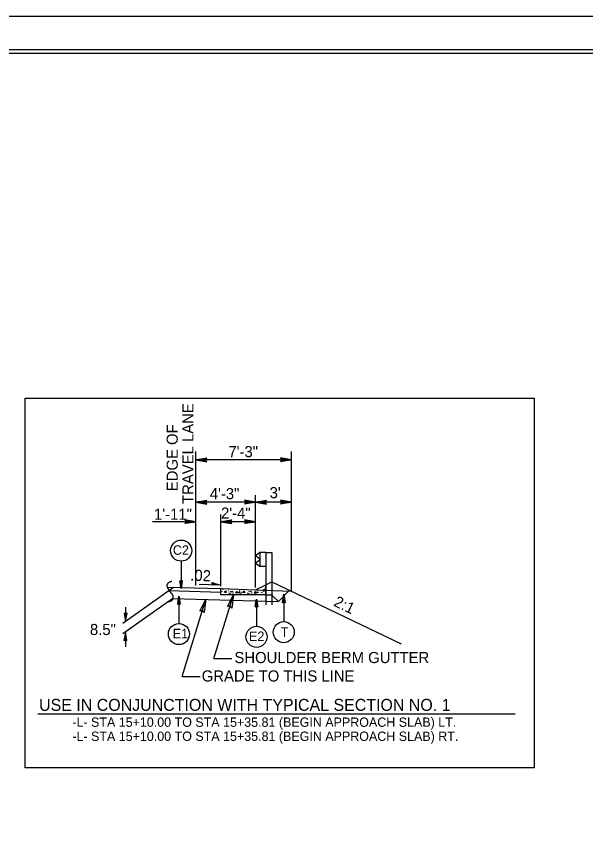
# Model space of a CAD drawing. Extents: x 55823 to 57507, y 47399 to 48499.
# Drawn here: x 56033 to 56415, y 47952 to 48499 of the extents above; entities that cross this region are included whole.
import ezdxf

# ---------------------------------------------------------------- set-up
doc = ezdxf.new("R2010")
doc.units = 0
for name, color, linetype in [('Old_Level_1', 7, 'Continuous'), ('Old_Level_11', 7, 'Continuous'), ('Old_Level_2', 7, 'Continuous'), ('Old_Level_20', 7, 'Continuous'), ('Sheet Plot Border Inside CELL', 7, 'Continuous'), ('Sheet Plot Border Outside CELL', 7, 'Continuous'), ('Sheet Typical CELL', 7, 'Continuous'), ('Typical Curb CELL', 7, 'Continuous')]:
    doc.layers.add(name, color=color, linetype=linetype)

msp = doc.modelspace()

# ---------------------------------------------------------------- linework, layer by layer
at = {"layer": 'Old_Level_1'}
for p, q in [((56153.74, 48117.93), (56153.74, 48207.72)), ((56217.76, 48114.25), (56217.76, 48207.72)), ((56217.76, 48202.2), (56153.74, 48202.2)), ((56153.75, 48202.17), (56161.12, 48203.47)), ((56153.75, 48202.17), (56160.98, 48203.29)), ((56160.84, 48203.1), (56153.75, 48202.17)), ((56153.75, 48202.17), (56160.7, 48202.91)), ((56160.57, 48202.73), (56153.75, 48202.17)), ((56153.75, 48202.17), (56160.43, 48202.54)), ((56160.3, 48202.36), (56153.75, 48202.17)), ((56153.75, 48202.17), (56161.12, 48200.87)), ((56160.98, 48201.06), (56153.75, 48202.17)), ((56153.75, 48202.17), (56160.84, 48201.24)), ((56160.7, 48201.43), (56153.75, 48202.17)), ((56153.75, 48202.17), (56160.57, 48201.62)), ((56160.43, 48201.8), (56153.75, 48202.17)), ((56153.75, 48202.17), (56160.3, 48201.99)), ((56160.16, 48202.17), (56153.75, 48202.17)), ((56160.16, 48202.17), (56161.12, 48203.47)), ((56161.12, 48200.87), (56160.16, 48202.17)), ((56217.76, 48202.2), (56210.4, 48203.5)), ((56210.4, 48203.5), (56211.35, 48202.2)), ((56217.76, 48202.2), (56210.4, 48200.9)), ((56211.35, 48202.2), (56210.4, 48200.9)), ((56210.53, 48203.31), (56217.76, 48202.2)), ((56217.76, 48202.2), (56210.53, 48201.08)), ((56217.76, 48202.2), (56210.67, 48203.13)), ((56210.67, 48201.27), (56217.76, 48202.2)), ((56210.81, 48202.94), (56217.76, 48202.2)), ((56217.76, 48202.2), (56210.81, 48201.46)), ((56217.76, 48202.2), (56210.94, 48202.76)), ((56210.94, 48201.64), (56217.76, 48202.2)), ((56211.08, 48202.57), (56217.76, 48202.2)), ((56217.76, 48202.2), (56211.08, 48201.83)), ((56217.76, 48202.2), (56211.21, 48202.39)), ((56211.21, 48202.01), (56217.76, 48202.2)), ((56211.35, 48202.2), (56217.76, 48202.2)), ((56193.74, 48116.69), (56193.74, 48178.64)), ((56153.74, 48173.91), (56161.11, 48175.21)), ((56153.74, 48173.91), (56160.97, 48175.03)), ((56160.83, 48174.84), (56153.74, 48173.91)), ((56153.74, 48173.91), (56160.7, 48174.65)), ((56160.56, 48174.47), (56153.74, 48173.91)), ((56153.74, 48173.91), (56160.43, 48174.28)), ((56160.29, 48174.1), (56153.74, 48173.91)), ((56193.74, 48173.91), (56153.74, 48173.91)), ((56153.74, 48173.91), (56161.11, 48172.61)), ((56160.97, 48172.8), (56153.74, 48173.91)), ((56153.74, 48173.91), (56160.83, 48172.98)), ((56160.7, 48173.17), (56153.74, 48173.91)), ((56153.74, 48173.91), (56160.56, 48173.35)), ((56160.43, 48173.54), (56153.74, 48173.91)), ((56153.74, 48173.91), (56160.29, 48173.72)), ((56160.15, 48173.91), (56153.74, 48173.91)), ((56160.15, 48173.91), (56161.11, 48175.21)), ((56161.11, 48172.61), (56160.15, 48173.91)), ((56193.74, 48173.91), (56186.37, 48175.21)), ((56186.37, 48175.21), (56187.33, 48173.91)), ((56193.74, 48173.91), (56186.37, 48172.61)), ((56187.33, 48173.91), (56186.37, 48172.61)), ((56186.51, 48175.02), (56193.74, 48173.91)), ((56193.74, 48173.91), (56186.51, 48172.79)), ((56193.74, 48173.91), (56186.65, 48174.84)), ((56186.65, 48172.98), (56193.74, 48173.91)), ((56186.78, 48174.65), (56193.74, 48173.91)), ((56193.74, 48173.91), (56186.78, 48173.17)), ((56193.74, 48173.91), (56186.92, 48174.47)), ((56186.92, 48173.35), (56193.74, 48173.91)), ((56187.05, 48174.28), (56193.74, 48173.91)), ((56193.74, 48173.91), (56187.05, 48173.54)), ((56193.74, 48173.91), (56187.19, 48174.1)), ((56187.19, 48173.72), (56193.74, 48173.91)), ((56187.33, 48173.91), (56193.74, 48173.91)), ((56193.74, 48173.91), (56201.11, 48175.21)), ((56193.74, 48173.91), (56200.97, 48175.03)), ((56200.83, 48174.84), (56193.74, 48173.91)), ((56193.74, 48173.91), (56200.7, 48174.65)), ((56200.56, 48174.47), (56193.74, 48173.91)), ((56193.74, 48173.91), (56200.43, 48174.28)), ((56200.29, 48174.1), (56193.74, 48173.91)), ((56217.76, 48173.91), (56193.74, 48173.91)), ((56193.74, 48173.91), (56201.11, 48172.61)), ((56200.97, 48172.8), (56193.74, 48173.91)), ((56193.74, 48173.91), (56200.83, 48172.98)), ((56200.7, 48173.17), (56193.74, 48173.91)), ((56193.74, 48173.91), (56200.56, 48173.35)), ((56200.43, 48173.54), (56193.74, 48173.91)), ((56193.74, 48173.91), (56200.29, 48173.72)), ((56200.15, 48173.91), (56193.74, 48173.91)), ((56200.15, 48173.91), (56201.11, 48175.21)), ((56201.11, 48172.61), (56200.15, 48173.91)), ((56217.76, 48173.91), (56210.4, 48175.21)), ((56210.4, 48175.21), (56211.35, 48173.91)), ((56217.76, 48173.91), (56210.4, 48172.61)), ((56211.35, 48173.91), (56210.4, 48172.61)), ((56210.53, 48175.02), (56217.76, 48173.91)), ((56217.76, 48173.91), (56210.53, 48172.79)), ((56217.76, 48173.91), (56210.67, 48174.84)), ((56210.67, 48172.98), (56217.76, 48173.91)), ((56210.81, 48174.65), (56217.76, 48173.91)), ((56217.76, 48173.91), (56210.81, 48173.17)), ((56217.76, 48173.91), (56210.94, 48174.47)), ((56210.94, 48173.35), (56217.76, 48173.91)), ((56211.08, 48174.28), (56217.76, 48173.91)), ((56217.76, 48173.91), (56211.08, 48173.54)), ((56217.76, 48173.91), (56211.21, 48174.1)), ((56211.21, 48173.72), (56217.76, 48173.91)), ((56211.35, 48173.91), (56217.76, 48173.91)), ((56153.74, 48160.76), (56124.7, 48160.76)), ((56153.74, 48160.76), (56146.37, 48162.06)), ((56146.37, 48162.06), (56147.33, 48160.76)), ((56153.74, 48160.76), (56146.37, 48159.46)), ((56147.33, 48160.76), (56146.37, 48159.46)), ((56146.51, 48161.88), (56153.74, 48160.76)), ((56153.74, 48160.76), (56146.51, 48159.65)), ((56153.74, 48160.76), (56146.65, 48161.69)), ((56146.65, 48159.83), (56153.74, 48160.76)), ((56146.78, 48161.5), (56153.74, 48160.76)), ((56153.74, 48160.76), (56146.78, 48160.02)), ((56153.74, 48160.76), (56146.92, 48161.32)), ((56146.92, 48160.21), (56153.74, 48160.76)), ((56147.05, 48161.14), (56153.74, 48160.76)), ((56153.74, 48160.76), (56147.05, 48160.39)), ((56153.74, 48160.76), (56147.19, 48160.95)), ((56147.19, 48160.58), (56153.74, 48160.76)), ((56147.33, 48160.76), (56153.74, 48160.76)), ((56170.41, 48117.53), (56170.41, 48165.52)), ((56170.41, 48160.76), (56177.78, 48162.06)), ((56170.41, 48160.76), (56177.64, 48161.88)), ((56177.5, 48161.69), (56170.41, 48160.76)), ((56170.41, 48160.76), (56177.37, 48161.51)), ((56177.23, 48161.32), (56170.41, 48160.76)), ((56170.41, 48160.76), (56177.1, 48161.14)), ((56176.96, 48160.95), (56170.41, 48160.76)), ((56193.74, 48160.76), (56170.41, 48160.76)), ((56170.41, 48160.76), (56177.78, 48159.46)), ((56177.64, 48159.65), (56170.41, 48160.76)), ((56170.41, 48160.76), (56177.5, 48159.84)), ((56177.37, 48160.02), (56170.41, 48160.76)), ((56170.41, 48160.76), (56177.23, 48160.21)), ((56177.1, 48160.39), (56170.41, 48160.76)), ((56170.41, 48160.76), (56176.96, 48160.58)), ((56176.82, 48160.76), (56170.41, 48160.76)), ((56176.82, 48160.76), (56177.78, 48162.06)), ((56177.78, 48159.46), (56176.82, 48160.76)), ((56193.74, 48160.76), (56186.37, 48162.06)), ((56186.37, 48162.06), (56187.33, 48160.76)), ((56193.74, 48160.76), (56186.37, 48159.46)), ((56187.33, 48160.76), (56186.37, 48159.46)), ((56186.51, 48161.88), (56193.74, 48160.76)), ((56193.74, 48160.76), (56186.51, 48159.65)), ((56193.74, 48160.76), (56186.65, 48161.69)), ((56186.65, 48159.83), (56193.74, 48160.76)), ((56186.78, 48161.5), (56193.74, 48160.76)), ((56193.74, 48160.76), (56186.78, 48160.02)), ((56193.74, 48160.76), (56186.92, 48161.32)), ((56186.92, 48160.21), (56193.74, 48160.76)), ((56187.05, 48161.14), (56193.74, 48160.76)), ((56193.74, 48160.76), (56187.05, 48160.39)), ((56193.74, 48160.76), (56187.19, 48160.95)), ((56187.19, 48160.58), (56193.74, 48160.76)), ((56187.33, 48160.76), (56193.74, 48160.76)), ((56196.59, 48140.04), (56194.25, 48138.39)), ((56200.61, 48140.04), (56196.59, 48140.04)), ((56196.59, 48140.04), (56196.59, 48130.65)), ((56200.61, 48140.04), (56200.61, 48111.77)), ((56200.61, 48140.04), (56204.64, 48140.04)), ((56204.64, 48140.04), (56204.64, 48119.93)), ((56196.59, 48135.72), (56194.25, 48137.36)), ((56196.59, 48134.97), (56194.25, 48133.33)), ((56196.59, 48135.35), (56196.59, 48135.72)), ((56196.59, 48135.35), (56196.59, 48134.97)), ((56196.59, 48130.65), (56194.25, 48132.3)), ((56200.61, 48130.65), (56196.59, 48130.65)), ((56138.7, 48116.76), (56104.6, 48092.53)), ((56134.55, 48116.87), (56170.41, 48115.94)), ((56143.79, 48116.06), (56142.88, 48121.24)), ((56143.79, 48120.56), (56142.88, 48121.24)), ((56143.79, 48116.06), (56143.01, 48121.14)), ((56143.14, 48121.04), (56143.79, 48116.06)), ((56143.79, 48116.06), (56143.27, 48120.95)), ((56143.4, 48120.85), (56143.79, 48116.06)), ((56143.79, 48116.06), (56143.53, 48120.76)), ((56143.66, 48120.66), (56143.79, 48116.06)), ((56143.79, 48116.06), (56144.7, 48121.24)), ((56144.7, 48121.24), (56143.79, 48120.56)), ((56144.57, 48121.14), (56143.79, 48116.06)), ((56143.79, 48116.06), (56144.44, 48121.04)), ((56144.31, 48120.95), (56143.79, 48116.06)), ((56143.79, 48116.06), (56144.18, 48120.85)), ((56144.05, 48120.76), (56143.79, 48116.06)), ((56143.79, 48116.06), (56143.92, 48120.66)), ((56143.79, 48120.56), (56143.79, 48116.06)), ((56155.8, 48118.95), (56169.5, 48118.57)), ((56164.62, 48119.85), (56164.66, 48119.81)), ((56164.7, 48119.75), (56164.77, 48119.75)), ((56164.76, 48119.62), (56165.24, 48119.63)), ((56165.67, 48119.49), (56164.81, 48119.53)), ((56164.85, 48119.38), (56166.2, 48119.34)), ((56164.85, 48119.25), (56166.74, 48119.18)), ((56164.85, 48118.86), (56168.66, 48118.71)), ((56164.86, 48119.16), (56167.48, 48119.02)), ((56164.86, 48119.06), (56167.79, 48118.92)), ((56164.86, 48118.77), (56169.03, 48118.62)), ((56164.88, 48118.96), (56168.25, 48118.82)), ((56200.61, 48118.54), (56204.64, 48120.56)), ((56204.64, 48119.93), (56204.64, 48111.77)), ((56135.65, 48114.67), (56170.41, 48113.64)), ((56142.32, 48110.8), (56141.4, 48105.62)), ((56141.54, 48105.71), (56142.32, 48110.8)), ((56142.32, 48110.8), (56141.67, 48105.81)), ((56141.8, 48105.91), (56142.32, 48110.8)), ((56142.32, 48110.8), (56141.93, 48106)), ((56142.06, 48106.1), (56142.32, 48110.8)), ((56142.32, 48110.8), (56142.19, 48106.19)), ((56142.32, 48110.8), (56143.23, 48105.62)), ((56142.32, 48106.29), (56142.32, 48110.8)), ((56142.45, 48106.19), (56142.32, 48110.8)), ((56142.32, 48110.8), (56142.58, 48106.1)), ((56142.71, 48106), (56142.32, 48110.8)), ((56142.32, 48110.8), (56142.84, 48105.91)), ((56142.97, 48105.81), (56142.32, 48110.8)), ((56142.32, 48110.8), (56143.1, 48105.71)), ((56165.8, 48069.12), (56178.87, 48111.77)), ((56193.74, 48115.11), (56217.76, 48114.25)), ((56200.61, 48111.77), (56204.64, 48111.77)), ((56200.61, 48111.77), (56200.61, 48105.12)), ((56200.61, 48111.77), (56204.64, 48111.65)), ((56204.64, 48111.77), (56204.64, 48105.12)), ((56204.64, 48111.65), (56208.98, 48107.32)), ((56216.51, 48114.85), (56208.98, 48107.32)), ((56138.25, 48109.4), (56104.68, 48085.55)), ((56138.25, 48109.4), (56208.98, 48107.32)), ((56141.4, 48105.62), (56142.32, 48106.29)), ((56142.32, 48106.29), (56143.23, 48105.62)), ((56144.53, 48057.14), (56160.33, 48108.75)), ((56194.29, 48108.97), (56193.38, 48103.79)), ((56193.51, 48103.89), (56194.29, 48108.97)), ((56194.29, 48108.97), (56193.64, 48103.98)), ((56193.77, 48104.08), (56194.29, 48108.97)), ((56194.29, 48108.97), (56193.9, 48104.17)), ((56194.03, 48104.27), (56194.29, 48108.97)), ((56194.29, 48108.97), (56194.16, 48104.36)), ((56194.29, 48108.97), (56195.21, 48103.79)), ((56194.29, 48104.46), (56194.29, 48108.97)), ((56194.42, 48104.36), (56194.29, 48108.97)), ((56194.29, 48108.97), (56194.55, 48104.27)), ((56194.68, 48104.17), (56194.29, 48108.97)), ((56194.29, 48108.97), (56194.81, 48104.08)), ((56194.94, 48103.98), (56194.29, 48108.97)), ((56194.29, 48108.97), (56195.07, 48103.89)), ((56193.38, 48103.79), (56194.29, 48104.46)), ((56194.29, 48104.46), (56195.21, 48103.79)), ((56165.8, 48069.12), (56177.74, 48069.12)), ((56144.53, 48057.14), (56156.56, 48057.14)), ((56047.68, 48032.1), (56367.7, 48032.1))]:
    msp.add_line(p, q, dxfattribs=at)
for points in [[(56137.58, 48120.7), (56137.56, 48120.7), (56137.53, 48120.7), (56137.51, 48120.7), (56137.48, 48120.7), (56137.46, 48120.7), (56137.44, 48120.7), (56137.44, 48120.68), (56137.39, 48120.68), (56137.34, 48120.65), (56137.27, 48120.65), (56137.2, 48120.63), (56137.1, 48120.61), (56137.03, 48120.58), (56136.96, 48120.56), (56136.86, 48120.51), (56136.76, 48120.49), (56136.67, 48120.46), (56136.57, 48120.41), (56136.48, 48120.37), (56136.38, 48120.34), (56136.31, 48120.32), (56136.21, 48120.27), (56136.14, 48120.25), (56136.07, 48120.2), (56135.97, 48120.17), (56135.9, 48120.13), (56135.83, 48120.1), (56135.76, 48120.05), (56135.69, 48120.01), (56135.64, 48119.98), (56135.57, 48119.96), (56135.52, 48119.91), (56135.47, 48119.89), (56135.4, 48119.84), (56135.38, 48119.82), (56135.3, 48119.79), (56135.28, 48119.74), (56135.26, 48119.74), (56135.21, 48119.72), (56135.16, 48119.67), (56135.14, 48119.65), (56135.06, 48119.6), (56135.04, 48119.55), (56134.97, 48119.5), (56134.9, 48119.46), (56134.85, 48119.41), (56134.8, 48119.36), (56134.73, 48119.29), (56134.7, 48119.24), (56134.66, 48119.19), (56134.63, 48119.14), (56134.61, 48119.12), (56134.59, 48119.07), (56134.56, 48119.05), (56134.54, 48119), (56134.49, 48118.95), (56134.47, 48118.88), (56134.44, 48118.83), (56134.39, 48118.76), (56134.37, 48118.69), (56134.32, 48118.62), (56134.3, 48118.54), (56134.3, 48118.47), (56134.27, 48118.38), (56134.25, 48118.31), (56134.23, 48118.23), (56134.23, 48118.16), (56134.23, 48118.07), (56134.23, 48118.02), (56134.23, 48117.95), (56134.23, 48117.87), (56134.23, 48117.8), (56134.23, 48117.75), (56134.23, 48117.68), (56134.23, 48117.63), (56134.25, 48117.56), (56134.25, 48117.47), (56134.27, 48117.42), (56134.3, 48117.32), (56134.32, 48117.25), (56134.35, 48117.18), (56134.37, 48117.08), (56134.42, 48116.99), (56134.47, 48116.89), (56134.51, 48116.8), (56134.56, 48116.7), (56134.61, 48116.6), (56134.63, 48116.51), (56134.7, 48116.39), (56134.75, 48116.27), (56134.8, 48116.17), (56134.85, 48116.08), (56134.9, 48115.98), (56134.94, 48115.86), (56134.99, 48115.77), (56135.04, 48115.67), (56135.09, 48115.57), (56135.14, 48115.48), (56135.21, 48115.38), (56135.26, 48115.31), (56135.3, 48115.21), (56135.38, 48115.12), (56135.42, 48115.02), (56135.5, 48114.93), (56135.54, 48114.83), (56135.62, 48114.76), (56135.69, 48114.66), (56135.76, 48114.57), (56135.83, 48114.47), (56135.9, 48114.38), (56135.97, 48114.26), (56136.05, 48114.16), (56136.12, 48114.09), (56136.21, 48113.97), (56136.29, 48113.9), (56136.33, 48113.8), (56136.41, 48113.73), (56136.48, 48113.63), (56136.55, 48113.56), (56136.62, 48113.46), (56136.69, 48113.39), (56136.76, 48113.3), (56136.84, 48113.22), (56136.91, 48113.13), (56136.98, 48113.03), (56137.05, 48112.96), (56137.12, 48112.87), (56137.17, 48112.79), (56137.24, 48112.72), (56137.32, 48112.63), (56137.39, 48112.55), (56137.44, 48112.48), (56137.48, 48112.43), (56137.56, 48112.34), (56137.63, 48112.27), (56137.67, 48112.19), (56137.72, 48112.12), (56137.77, 48112.05), (56137.82, 48111.95), (56137.87, 48111.88), (56137.91, 48111.79), (56137.96, 48111.69), (56138.01, 48111.6), (56138.06, 48111.52), (56138.08, 48111.43), (56138.13, 48111.36), (56138.13, 48111.28), (56138.15, 48111.21), (56138.15, 48111.14), (56138.18, 48111.04), (56138.18, 48111), (56138.2, 48110.9), (56138.2, 48110.83), (56138.23, 48110.76), (56138.23, 48110.68), (56138.23, 48110.59), (56138.23, 48110.52), (56138.23, 48110.42), (56138.25, 48110.33), (56138.25, 48110.23), (56138.25, 48110.11), (56138.25, 48110.01), (56138.25, 48109.92), (56138.25, 48109.8), (56138.25, 48109.68), (56138.25, 48109.56), (56138.25, 48109.44), (56138.23, 48109.32), (56138.2, 48109.29), (56138.2, 48109.22), (56138.18, 48109.1), (56138.15, 48109.01), (56138.11, 48108.91), (56138.08, 48108.79), (56138.01, 48108.67), (56137.96, 48108.58), (56137.89, 48108.48), (56137.84, 48108.36), (56137.77, 48108.26), (56137.67, 48108.17), (56137.6, 48108.1), (56137.53, 48108), (56137.48, 48107.95), (56137.41, 48107.88), (56137.34, 48107.83), (56137.27, 48107.78), (56137.2, 48107.74), (56137.15, 48107.69), (56137.1, 48107.64), (56137.03, 48107.62), (56136.98, 48107.57), (56136.91, 48107.55), (56136.84, 48107.52), (56136.79, 48107.47), (56136.72, 48107.45), (56136.65, 48107.4), (56136.57, 48107.38), (56136.53, 48107.35), (56136.48, 48107.33), (56136.41, 48107.31), (56136.36, 48107.31), (56136.31, 48107.28), (56136.24, 48107.26), (56136.17, 48107.23), (56136.09, 48107.21), (56136.02, 48107.19), (56135.93, 48107.16), (56135.88, 48107.14), (56135.78, 48107.11), (56135.71, 48107.09), (56135.62, 48107.07), (56135.54, 48107.04), (56135.47, 48107.04), (56135.4, 48107.02), (56135.33, 48106.99), (56135.28, 48106.97), (56135.21, 48106.97), (56135.14, 48106.95), (56135.06, 48106.92), (56134.99, 48106.9), (56134.94, 48106.87), (56134.87, 48106.85), (56134.8, 48106.85), (56134.73, 48106.8), (56134.7, 48106.8), (56134.66, 48106.78), (56134.63, 48106.78), (56134.61, 48106.73), (56134.56, 48106.73), (56134.49, 48106.71), (56134.47, 48106.68), (56134.42, 48106.68), (56134.37, 48106.63), (56134.32, 48106.63), (56134.3, 48106.61), (56134.27, 48106.61), (56134.25, 48106.61), (56134.25, 48106.63)], [(56204.64, 48120.56), (56291.34, 48078.89)]]:
    msp.add_lwpolyline(points, dxfattribs=at)
for centre, radius, start, end in [((56194.61, 48137.88), 0.628, 125.003, 235.0112), ((56194.61, 48132.81), 0.628, 125.0059, 235.0366), ((56180.67, 48168.56), 51.22, 251.5746, 257.4084), ((56162.11, 48118.92), 2.6, 355.8477, 23.7953)]:
    msp.add_arc(centre, radius, start, end, dxfattribs=at)
at = {"layer": 'Old_Level_11'}
for points in [[(56039.24, 48243.59), (56380.49, 48243.59), (56380.49, 47995.89), (56039.24, 47995.89)], [(56174.87, 48103.87), (56178.87, 48111.77), (56177.78, 48102.93), (56176.62, 48104.45)], [(56211.64, 48106.41), (56212.57, 48112.1), (56213.61, 48106.41), (56212.57, 48107.13)], [(56156.34, 48100.85), (56160.33, 48108.75), (56159.25, 48099.91), (56158.09, 48101.43)], [(56105.57, 48099.57), (56106.5, 48093.88), (56107.53, 48099.57), (56106.5, 48098.84)], [(56107.44, 48081.15), (56106.51, 48086.84), (56105.47, 48081.15), (56106.51, 48081.88)]]:
    msp.add_lwpolyline(points, close=True, dxfattribs=at)
at = {"layer": 'Old_Level_2'}
for p, q in [((56143.79, 48134.32), (56143.79, 48116.06)), ((56142.32, 48110.8), (56142.32, 48092.53)), ((56212.57, 48112.1), (56212.57, 48093.83)), ((56194.29, 48108.97), (56194.29, 48090.7)), ((56106.5, 48103.56), (56106.5, 48093.88)), ((56106.51, 48086.84), (56106.51, 48077.03))]:
    msp.add_line(p, q, dxfattribs=at)
for centre in [(56143.79, 48141.39), (56142.32, 48085.46), (56194.29, 48083.64), (56212.57, 48086.76)]:
    msp.add_circle(centre, 7.07, dxfattribs=at)
at = {"layer": 'Sheet Plot Border Inside CELL'}
msp.add_lwpolyline([(57502.66, 48476.93), (55836.16, 48476.93), (55836.16, 47421.83), (57502.66, 47421.83)], close=True, dxfattribs=at)
at = {"layer": 'Sheet Plot Border Outside CELL'}
msp.add_lwpolyline([(57507.16, 48499.38), (55823.16, 48499.38), (55823.16, 47399.38), (57507.16, 47399.38)], close=True, dxfattribs=at)
at = {"layer": 'Sheet Typical CELL'}
msp.add_lwpolyline([(57490.16, 48474.38), (55990.16, 48474.38), (55990.16, 47424.38), (57490.16, 47424.38)], close=True, dxfattribs=at)
at = {"layer": 'Typical Curb CELL'}
for p, q in [((56193.74, 48115.11), (56200.61, 48118.54)), ((56200.61, 48111.77), (56200.61, 48118.54)), ((56170.41, 48115.94), (56170.41, 48115.94)), ((56170.41, 48111.77), (56170.41, 48115.83)), ((56200.61, 48111.77), (56170.41, 48111.77)), ((56170.52, 48115.94), (56193.74, 48115.11)), ((56172.78, 48113.29), (56173.65, 48114.49)), ((56173.99, 48113.35), (56172.78, 48113.29)), ((56173.65, 48114.49), (56173.99, 48113.35)), ((56180.44, 48112.78), (56181.06, 48113.93)), ((56182.1, 48113.18), (56180.44, 48112.78)), ((56181.06, 48113.93), (56182.1, 48113.18)), ((56185.28, 48113.29), (56186.14, 48114.49)), ((56186.48, 48113.35), (56185.28, 48113.29)), ((56186.14, 48114.49), (56186.48, 48113.35)), ((56192.93, 48112.78), (56193.55, 48113.93)), ((56194.58, 48113.18), (56192.93, 48112.78)), ((56193.55, 48113.93), (56194.58, 48113.18)), ((56198.71, 48115.21), (56198.87, 48114.3)), ((56200.25, 48114.76), (56198.71, 48115.21)), ((56198.87, 48114.3), (56200.25, 48114.76))]:
    msp.add_line(p, q, dxfattribs=at)
for centre in [(56171.31, 48114.16), (56171.69, 48115.41), (56175.36, 48114.67), (56175.95, 48112.88), (56176.51, 48112.54), (56176.84, 48113.81), (56177.6, 48113.79), (56178.1, 48114.1), (56178.57, 48112.94), (56180.51, 48113.33), (56182.57, 48113.17), (56182.74, 48113.68), (56182.84, 48114.27), (56183.41, 48112.84), (56184.37, 48113.3), (56185.3, 48113.39), (56186.5, 48112.88), (56188.44, 48112.88), (56189, 48112.54), (56189.33, 48113.81), (56190.59, 48114.1), (56191.06, 48112.94), (56193, 48113.33), (56193.29, 48112.31), (56195.06, 48113.17), (56195.23, 48113.68), (56197.8, 48113.39), (56198.99, 48112.88), (56199.97, 48115.62)]:
    msp.add_circle(centre, 0.0802, dxfattribs=at)
msp.add_arc((56170.51, 48115.83), 0.104, 87.952, 180, dxfattribs=at)

# ---------------------------------------------------------------- texts
at = {"layer": 'Old_Level_1'}
for s, height, rotation, p in [('TRAVEL LANE', 7.4468, 90, (56152.07, 48172.65)), ('EDGE OF', 7.447, 90, (56141.53, 48181.19)), (' .02', 7.447, 357.1962, (56147.01, 48121.53)), ('2:1', 7.447, 334.3354, (56245.44, 48104.63))]:
    msp.add_text(s, height=height, rotation=rotation, dxfattribs=at).set_placement(p)
for s, height, p in [('7\'-3"', 7.447, (56175.49, 48204)), ('4\'-3"', 7.447, (56163, 48175.84)), ("3'", 7.447, (56203.12, 48176.49)), ('1\'-11"', 7.447, (56125.64, 48162.06)), ('2\'-4"', 7.447, (56170.52, 48162.8)), ('8.5"', 7.447, (56082.66, 48084.82)), ('SHOULDER BERM GUTTER', 7.4468, (56179.51, 48066.02)), ('GRADE TO THIS LINE', 7.4468, (56157.59, 48053.69)), ('USE IN CONJUNCTION WITH TYPICAL SECTION NO. 1 ', 8, (56048.57, 48034.03)), ('-L- STA 15+10.00 TO STA 15+35.81 (BEGIN APPROACH SLAB) LT.', 6.25, (56070.87, 48023.32)), ('-L- STA 15+10.00 TO STA 15+35.81 (BEGIN APPROACH SLAB) RT.', 6.25, (56070.87, 48013.88))]:
    msp.add_text(s, height=height, dxfattribs=at).set_placement(p)
at = {"layer": 'Old_Level_20'}
for s, height, p in [('C2', 6.327, (56138.23, 48138.6)), ('E1', 6.327, (56138.18, 48082.68)), ('T', 6.33, (56210.47, 48083.6)), ('E2', 6.327, (56189.24, 48080.85))]:
    msp.add_text(s, height=height, dxfattribs=at).set_placement(p)

doc.saveas('drawing.dxf')
